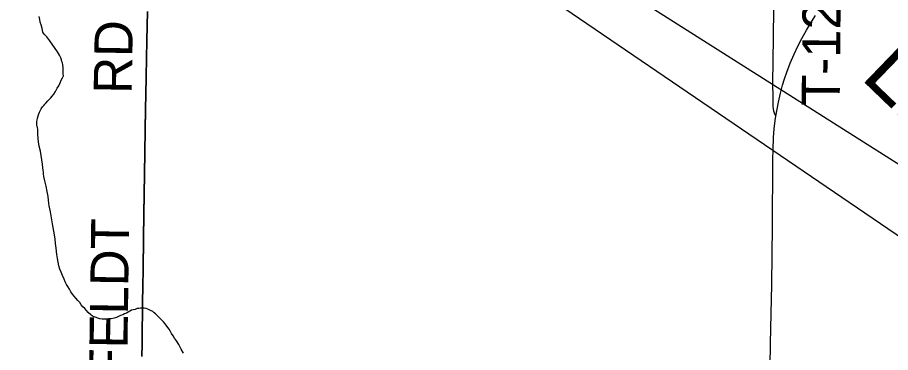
# Model space of a CAD drawing. Extents: x 0 to 34, y 0 to 22.
# Drawn here: x 6.454 to 7.757, y 15.755 to 16.256 of the extents above; entities that cross this region are included whole.
import ezdxf

# ---------------------------------------------------------------- set-up
doc = ezdxf.new("R2010")
doc.units = 0
for name, color, linetype in [('GM_X_County_Text', 7, 'Continuous'), ('GM_X_Minor_River', 7, 'Continuous'), ('GM_X_Minor_River_Text', 7, 'Continuous'), ('GM_X_Township_Road', 7, 'Continuous'), ('GM_X_Township_Road_Text', 7, 'Continuous'), ('GM_X_US_Route', 7, 'Continuous'), ('TX_P_1', 7, 'Continuous')]:
    doc.layers.add(name, color=color, linetype=linetype)

msp = doc.modelspace()

# ---------------------------------------------------------------- linework, layer by layer
at = {"layer": 'GM_X_County_Text'}
for points in [[(6.6397, 15.7499), (6.6398, 15.7673), (6.64, 15.7891), (6.6404, 15.8146), (6.6405, 15.8307), (6.641, 15.8538), (6.6415, 15.8798), (6.6421, 15.9265), (6.6427, 15.9619), (6.6436, 16.0222), (6.6451, 16.1198), (6.6454, 16.1404), (6.646, 16.1677), (6.6468, 16.2212), (6.6478, 16.2647)], [(6.6478, 16.2647), (6.6468, 16.2212), (6.646, 16.1677), (6.6454, 16.1404), (6.6451, 16.1198), (6.6436, 16.0222), (6.6427, 15.9619), (6.6421, 15.9265), (6.6415, 15.8798), (6.641, 15.8538), (6.6405, 15.8307), (6.6404, 15.8146), (6.64, 15.7891), (6.6398, 15.7673), (6.6397, 15.7499)]]:
    msp.add_lwpolyline(points, dxfattribs=at)
at = {"layer": 'GM_X_Minor_River'}
for points in [[(6.492, 16.0313), (6.4914, 16.0366), (6.4881, 16.0561), (6.4863, 16.0633), (6.4853, 16.0702), (6.4847, 16.0744), (6.4847, 16.077), (6.4844, 16.0797), (6.4845, 16.0831), (6.4842, 16.0877), (6.4836, 16.0919), (6.4829, 16.0938), (6.483, 16.0976), (6.483, 16.1002), (6.4835, 16.1025), (6.4839, 16.1055), (6.4847, 16.1086), (6.4856, 16.112), (6.4868, 16.1142), (6.488, 16.1165), (6.4895, 16.1191), (6.4915, 16.1225), (6.4931, 16.1243), (6.4946, 16.1262), (6.4962, 16.128), (6.4993, 16.1314), (6.5013, 16.1332), (6.5036, 16.1355), (6.5055, 16.1381), (6.5083, 16.1414), (6.5106, 16.1452), (6.513, 16.1501), (6.5158, 16.1538), (6.5178, 16.1579), (6.5194, 16.1621), (6.521, 16.1658), (6.5226, 16.1688), (6.5223, 16.1715), (6.5223, 16.1741), (6.522, 16.1772), (6.5221, 16.1806), (6.5218, 16.1848), (6.5211, 16.1878), (6.5204, 16.1901), (6.5197, 16.1924), (6.5187, 16.1955), (6.5169, 16.1993), (6.5139, 16.2044), (6.5022, 16.221), (6.4978, 16.2268), (6.4937, 16.231), (6.4918, 16.2337), (6.4908, 16.2395), (6.4895, 16.2448), (6.488, 16.2486), (6.4874, 16.2525), (6.4863, 16.257)], [(6.7015, 15.7543), (6.6983, 15.7604), (6.6946, 15.7674), (6.6913, 15.7728), (6.6884, 15.777), (6.6862, 15.7805), (6.684, 15.7839), (6.6822, 15.787), (6.6804, 15.7901), (6.677, 15.7948), (6.6745, 15.7982), (6.6719, 15.801), (6.6697, 15.8033), (6.6678, 15.8052), (6.6659, 15.8072), (6.663, 15.8103), (6.66, 15.813), (6.6581, 15.8146), (6.6559, 15.8165), (6.6525, 15.8181), (6.6503, 15.8193), (6.6484, 15.8201), (6.6462, 15.8209), (6.6431, 15.8214), (6.6397, 15.8215), (6.6374, 15.8215), (6.6351, 15.8212), (6.6325, 15.8209), (6.6294, 15.8198), (6.6267, 15.8191), (6.6241, 15.8184), (6.6218, 15.817), (6.6191, 15.8155), (6.6168, 15.8144), (6.6137, 15.813), (6.611, 15.8119), (6.6079, 15.8105), (6.6049, 15.8094), (6.6018, 15.8079), (6.5984, 15.8069), (6.5938, 15.8059), (6.5896, 15.8056), (6.5862, 15.8053), (6.5835, 15.8053), (6.5805, 15.8054), (6.5771, 15.8059), (6.5684, 15.8087), (6.5658, 15.8099), (6.5632, 15.8119), (6.5595, 15.8154), (6.5569, 15.8181), (6.5543, 15.8209), (6.5517, 15.8236), (6.5491, 15.8267), (6.5469, 15.8301), (6.5439, 15.8333), (6.541, 15.8364), (6.5384, 15.8395), (6.5362, 15.8426), (6.5336, 15.846), (6.5314, 15.8499), (6.5289, 15.8538), (6.527, 15.8572), (6.5252, 15.8611), (6.5234, 15.8649), (6.5213, 15.8703), (6.5191, 15.8753), (6.5173, 15.8799), (6.5159, 15.8848), (6.5149, 15.8902), (6.5139, 15.8959), (6.5129, 15.902), (6.5116, 15.9111), (6.5106, 15.9184), (6.51, 15.9249), (6.509, 15.931), (6.508, 15.9367), (6.5074, 15.942), (6.5064, 15.9474), (6.5054, 15.9535), (6.5044, 15.9596), (6.503, 15.9653), (6.502, 15.9699), (6.5013, 15.9745), (6.501, 15.9783), (6.5004, 15.9828), (6.4998, 15.9885), (6.4984, 15.9958), (6.4967, 16.0038), (6.495, 16.0118), (6.4932, 16.0183), (6.4926, 16.0221), (6.4926, 16.0248), (6.4923, 16.0279), (6.492, 16.0313)]]:
    msp.add_lwpolyline(points, dxfattribs=at)
at = {"layer": 'GM_X_Township_Road'}
for points in [[(7.5856, 16.1081), (7.5835, 16.1126), (7.5825, 16.116), (7.582, 16.1194), (7.5818, 16.1226), (7.5815, 16.1346), (7.5814, 16.1591), (7.5816, 16.1896), (7.5829, 16.2666), (7.5836, 16.3082), (7.5838, 16.3274), (7.5838, 16.3479), (7.5836, 16.3641), (7.5835, 16.3746), (7.583, 16.3907), (7.5826, 16.3963), (7.5819, 16.4012), (7.5808, 16.4061), (7.5794, 16.4108), (7.5789, 16.412), (7.5766, 16.4183)], [(6.6399, 15.7494), (6.64, 15.7668), (6.6402, 15.7885), (6.6406, 15.814), (6.6407, 15.8302), (6.6412, 15.8532), (6.6418, 15.8793), (6.6423, 15.9259), (6.6429, 15.9614), (6.6438, 16.0217), (6.6453, 16.1193), (6.6457, 16.1398), (6.6463, 16.1672), (6.647, 16.2206), (6.648, 16.2642)]]:
    msp.add_lwpolyline(points, dxfattribs=at)
at = {"layer": 'GM_X_US_Route'}
msp.add_lwpolyline([(7.5772, 15.7347), (7.5779, 15.7688), (7.5787, 15.8136), (7.5796, 15.8565), (7.5804, 15.9019), (7.5807, 15.9429), (7.5811, 16.0405), (7.5815, 16.0617), (7.582, 16.073), (7.5821, 16.0765), (7.5832, 16.0895), (7.5847, 16.1018), (7.5856, 16.1081), (7.5896, 16.1293), (7.5927, 16.1426), (7.5959, 16.1546), (7.5988, 16.164), (7.6022, 16.174), (7.6073, 16.1873), (7.6131, 16.2011), (7.6186, 16.2129), (7.6245, 16.2245), (7.6314, 16.237), (7.6387, 16.2492), (7.6448, 16.2586)], dxfattribs=at)
at = {"layer": 'TX_P_1'}
msp.add_lwpolyline([(9.2734, 14.9035), (5.5187, 17.4627), (9.2734, 15.0836)], close=True, dxfattribs=at)

# ---------------------------------------------------------------- texts
at = {"layer": 'GM_X_Minor_River_Text'}
msp.add_text('Lick', height=0.09475, rotation=316.0476, dxfattribs=at).set_placement((7.7105, 16.1657))
at = {"layer": 'GM_X_Township_Road_Text'}
for s, rotation, p in [('T-127', 89.4437, (7.681, 16.1235)), ('RD', 89.0151, (6.6244, 16.1414)), ('BEHNFELDT', 89.1795, (6.6144, 15.5037))]:
    msp.add_text(s, height=0.05682, rotation=rotation, dxfattribs=at).set_placement(p)

doc.saveas('drawing.dxf')
